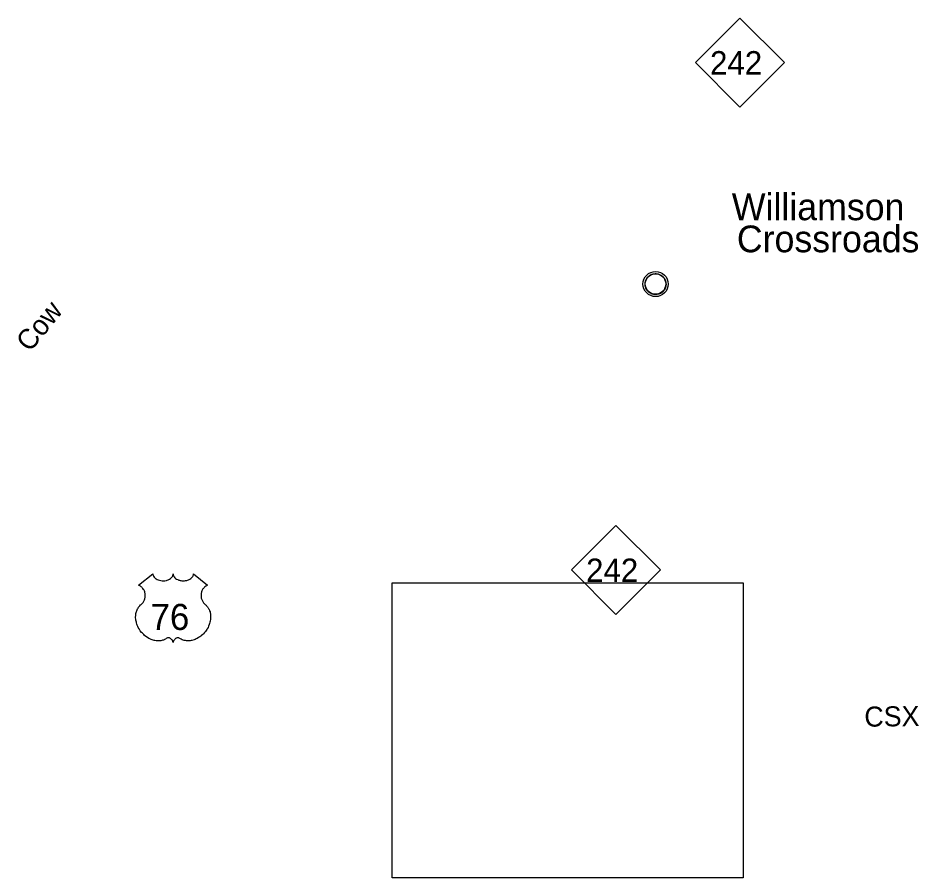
# Model space of a CAD drawing. Extents: x 5197761 to 5514561, y 1890130 to 2080942.
# Drawn here: x 5235501 to 5262490, y 2005464 to 2031207 of the extents above; entities that cross this region are included whole.
import ezdxf

# ---------------------------------------------------------------- set-up
doc = ezdxf.new("R2010")
doc.units = 0
for name, color, linetype in [('Exist Civil Demographics Community CELL', 7, 'Continuous'), ('Exist Civil Demographics Community Label', 7, 'Continuous'), ('Exist Hydrographic Creek Single Shore Label', 7, 'Continuous'), ('Exist Railroad Mainline Label', 7, 'Continuous'), ('Exist Road Primary NC Shield CELL', 7, 'Continuous'), ('Exist Road Primary NC Shield Number Label', 7, 'Continuous'), ('Exist Road Primary US Shield CELL', 7, 'Continuous'), ('Exist Road Primary US Shield Number Label', 7, 'Continuous'), ('Map Preparation Inset Cut Line', 7, 'Continuous')]:
    doc.layers.add(name, color=color, linetype=linetype)

msp = doc.modelspace()

# ---------------------------------------------------------------- linework, layer by layer
at = {"layer": 'Exist Civil Demographics Community CELL'}
msp.add_lwpolyline([(5254289, 2023293), (5254293, 2023316), (5254300, 2023342), (5254311, 2023371), (5254323, 2023394), (5254336, 2023417), (5254351, 2023437), (5254367, 2023455), (5254386, 2023473), (5254408, 2023492), (5254430, 2023506), (5254449, 2023518), (5254469, 2023527), (5254491, 2023537), (5254514, 2023544), (5254531, 2023549), (5254550, 2023551), (5254567, 2023554), (5254592, 2023555), (5254610, 2023555), (5254633, 2023554), (5254652, 2023551), (5254672, 2023547), (5254692, 2023541), (5254713, 2023534), (5254739, 2023522), (5254764, 2023508), (5254785, 2023494), (5254805, 2023478), (5254818, 2023465), (5254835, 2023448), (5254850, 2023429), (5254863, 2023411), (5254875, 2023391), (5254885, 2023370), (5254893, 2023350), (5254899, 2023330), (5254905, 2023311), (5254909, 2023287), (5254911, 2023268), (5254912, 2023244), (5254912, 2023221), (5254909, 2023198), (5254906, 2023177), (5254899, 2023152), (5254892, 2023129), (5254882, 2023108), (5254870, 2023084), (5254857, 2023063), (5254843, 2023044), (5254826, 2023025), (5254805, 2023005), (5254785, 2022989), (5254765, 2022975), (5254747, 2022965), (5254720, 2022952), (5254692, 2022941), (5254668, 2022936), (5254641, 2022930), (5254624, 2022928), (5254606, 2022927), (5254583, 2022927), (5254566, 2022929), (5254544, 2022932), (5254520, 2022937), (5254502, 2022942), (5254481, 2022950), (5254463, 2022958), (5254447, 2022967), (5254420, 2022983), (5254397, 2023000), (5254378, 2023018), (5254360, 2023038), (5254347, 2023053), (5254335, 2023070), (5254319, 2023099), (5254312, 2023113), (5254305, 2023129), (5254295, 2023162), (5254289, 2023190), (5254286, 2023210), (5254285, 2023236), (5254284, 2023254), (5254287, 2023280)], close=True, dxfattribs=at)
for centre, radius in [((5254599, 2023244), 377), ((5254598, 2023245), 307)]:
    msp.add_circle(centre, radius, dxfattribs=at)
at = {"layer": 'Exist Road Primary NC Shield CELL'}
for points in [[(5255795, 2029875), (5257127, 2031207), (5258459, 2029875), (5257127, 2028543)], [(5252081, 2014684), (5253413, 2016016), (5254745, 2014684), (5253413, 2013352)]]:
    msp.add_lwpolyline(points, close=True, dxfattribs=at)
at = {"layer": 'Exist Road Primary US Shield CELL'}
msp.add_lwpolyline([(5239539, 2014564), (5239540, 2014546), (5239545, 2014525), (5239548, 2014514), (5239558, 2014494), (5239574, 2014469), (5239596, 2014445), (5239622, 2014425), (5239639, 2014414), (5239668, 2014398), (5239700, 2014384), (5239737, 2014374), (5239775, 2014366), (5239815, 2014362), (5239856, 2014361), (5239900, 2014364), (5239948, 2014373), (5239970, 2014379), (5239995, 2014388), (5240018, 2014397), (5240043, 2014411), (5240064, 2014424), (5240080, 2014435), (5240102, 2014457), (5240120, 2014479), (5240128, 2014492), (5240134, 2014504), (5240143, 2014530), (5240146, 2014541), (5240148, 2014564), (5240149, 2014545), (5240151, 2014532), (5240154, 2014520), (5240159, 2014507), (5240168, 2014489), (5240178, 2014474), (5240197, 2014452), (5240209, 2014441), (5240220, 2014432), (5240249, 2014412), (5240283, 2014395), (5240299, 2014388), (5240316, 2014382), (5240338, 2014375), (5240360, 2014370), (5240382, 2014366), (5240405, 2014363), (5240428, 2014361), (5240447, 2014361), (5240470, 2014361), (5240491, 2014362), (5240513, 2014365), (5240537, 2014369), (5240556, 2014373), (5240582, 2014380), (5240605, 2014388), (5240626, 2014397), (5240652, 2014411), (5240673, 2014424), (5240689, 2014437), (5240707, 2014454), (5240725, 2014474), (5240735, 2014489), (5240743, 2014504), (5240749, 2014520), (5240753, 2014537), (5240755, 2014552), (5240756, 2014565), (5241181, 2014226), (5241171, 2014222), (5241148, 2014211), (5241130, 2014200), (5241100, 2014180), (5241088, 2014168), (5241075, 2014157), (5241064, 2014144), (5241053, 2014132), (5241041, 2014115), (5241030, 2014098), (5241019, 2014079), (5241011, 2014063), (5240998, 2014029), (5240992, 2014007), (5240988, 2013989), (5240983, 2013951), (5240982, 2013933), (5240982, 2013915), (5240983, 2013896), (5240985, 2013878), (5240988, 2013859), (5240991, 2013843), (5240996, 2013822), (5241004, 2013799), (5241013, 2013776), (5241032, 2013739), (5241057, 2013701), (5241075, 2013680), (5241093, 2013662), (5241119, 2013640), (5241133, 2013627), (5241150, 2013611), (5241176, 2013580), (5241187, 2013565), (5241198, 2013549), (5241208, 2013532), (5241218, 2013514), (5241226, 2013498), (5241241, 2013462), (5241252, 2013427), (5241257, 2013408), (5241265, 2013366), (5241268, 2013346), (5241271, 2013305), (5241271, 2013256), (5241267, 2013209), (5241259, 2013155), (5241251, 2013122), (5241240, 2013084), (5241229, 2013051), (5241210, 2013003), (5241193, 2012967), (5241170, 2012926), (5241155, 2012901), (5241137, 2012875), (5241115, 2012844), (5241089, 2012811), (5241057, 2012777), (5241032, 2012752), (5240999, 2012722), (5240979, 2012705), (5240950, 2012684), (5240911, 2012658), (5240872, 2012635), (5240839, 2012618), (5240810, 2012606), (5240773, 2012592), (5240710, 2012574), (5240687, 2012570), (5240660, 2012565), (5240635, 2012563), (5240610, 2012561), (5240577, 2012561), (5240544, 2012564), (5240513, 2012568), (5240480, 2012575), (5240447, 2012585), (5240416, 2012597), (5240385, 2012613), (5240332, 2012646), (5240317, 2012654), (5240308, 2012656), (5240288, 2012657), (5240269, 2012653), (5240249, 2012645), (5240238, 2012639), (5240222, 2012629), (5240210, 2012619), (5240195, 2012605), (5240185, 2012594), (5240178, 2012585), (5240163, 2012561), (5240157, 2012550), (5240152, 2012536), (5240147, 2012515), (5240140, 2012542), (5240133, 2012559), (5240124, 2012574), (5240114, 2012588), (5240099, 2012605), (5240086, 2012617), (5240070, 2012631), (5240053, 2012641), (5240039, 2012648), (5240027, 2012653), (5240011, 2012656), (5239999, 2012657), (5239988, 2012657), (5239974, 2012654), (5239955, 2012640), (5239937, 2012628), (5239917, 2012615), (5239893, 2012603), (5239876, 2012595), (5239856, 2012587), (5239831, 2012579), (5239805, 2012572), (5239778, 2012566), (5239755, 2012563), (5239729, 2012560), (5239707, 2012560), (5239683, 2012560), (5239660, 2012562), (5239635, 2012564), (5239602, 2012569), (5239576, 2012575), (5239548, 2012582), (5239519, 2012591), (5239488, 2012603), (5239449, 2012620), (5239422, 2012634), (5239380, 2012658), (5239330, 2012693), (5239293, 2012723), (5239265, 2012748), (5239225, 2012789), (5239201, 2012816), (5239164, 2012864), (5239140, 2012899), (5239125, 2012925), (5239102, 2012966), (5239090, 2012992), (5239073, 2013029), (5239061, 2013064), (5239050, 2013097), (5239045, 2013117), (5239037, 2013154), (5239032, 2013180), (5239027, 2013215), (5239024, 2013253), (5239024, 2013287), (5239025, 2013316), (5239028, 2013349), (5239034, 2013384), (5239040, 2013415), (5239046, 2013437), (5239056, 2013463), (5239067, 2013493), (5239082, 2013521), (5239095, 2013544), (5239112, 2013569), (5239128, 2013591), (5239150, 2013614), (5239173, 2013636), (5239193, 2013653), (5239218, 2013677), (5239231, 2013691), (5239246, 2013712), (5239259, 2013731), (5239268, 2013747), (5239281, 2013772), (5239289, 2013791), (5239299, 2013819), (5239304, 2013840), (5239309, 2013865), (5239312, 2013890), (5239313, 2013920), (5239312, 2013945), (5239309, 2013975), (5239304, 2014003), (5239297, 2014027), (5239287, 2014056), (5239277, 2014076), (5239261, 2014104), (5239242, 2014130), (5239224, 2014151), (5239205, 2014170), (5239187, 2014184), (5239170, 2014196), (5239148, 2014209), (5239127, 2014220), (5239114, 2014225)], close=True, dxfattribs=at)
at = {"layer": 'Map Preparation Inset Cut Line'}
msp.add_lwpolyline([(5246708, 2014304), (5257223, 2014304), (5257223, 2005464), (5246708, 2005464)], close=True, dxfattribs=at)

# ---------------------------------------------------------------- texts
at = {"layer": 'Exist Civil Demographics Community Label'}
for s, p in [('Williamson', (5256883, 2025155)), ('Crossroads', (5257034, 2024195))]:
    msp.add_text(s, height=800, dxfattribs=at).set_placement(p)
at = {"layer": 'Exist Hydrographic Creek Single Shore Label'}
msp.add_text('Cow', height=600, rotation=50.9457, dxfattribs=at).set_placement((5235858, 2021181))
at = {"layer": 'Exist Railroad Mainline Label'}
msp.add_text('CSX', height=600, rotation=0.7758, dxfattribs=at).set_placement((5260857, 2009991))
at = {"layer": 'Exist Road Primary NC Shield Number Label'}
for p in [(5256231, 2029516), (5252518, 2014325)]:
    msp.add_text('242', height=700, dxfattribs=at).set_placement(p)
at = {"layer": 'Exist Road Primary US Shield Number Label'}
msp.add_text('76', height=780, dxfattribs=at).set_placement((5239471, 2012889))

doc.saveas('drawing.dxf')
